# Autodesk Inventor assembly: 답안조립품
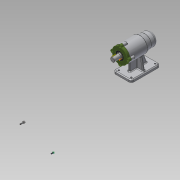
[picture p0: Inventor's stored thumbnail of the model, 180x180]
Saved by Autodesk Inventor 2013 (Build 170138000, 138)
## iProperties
Created: 2019-07
Part Number: 답안조립품
Document SubType Name: Assembly
Designer: Administrator
Author: Administrator
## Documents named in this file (12)
- C:\Users\Administrator\Desktop\490704V1055\답안조립품.iam
- C:\Users\Administrator\Desktop\490704V1055\본체.ipt
- C:\Users\Administrator\Desktop\490704V1055\V벨트풀리.ipt
- C:\Users\Administrator\Desktop\490704V1055\멈춤나사 M3.ipt
- C:\Users\Administrator\Desktop\490704V1055\베어링 6004.ipt
- C:\Users\Administrator\Desktop\490704V1055\베어링 51202.ipt
- C:\Users\Administrator\Desktop\490704V1055\볼트 M4.ipt
- C:\Users\Administrator\Desktop\490704V1055\어댑터슬리브.ipt
- C:\Users\Administrator\Desktop\490704V1055\오일 실.ipt
- C:\Users\Administrator\Desktop\490704V1055\축.ipt
- C:\Users\Administrator\Desktop\490704V1055\커버.ipt
- C:\Users\Administrator\Desktop\490704V1055\키 5 x 5 x 16.ipt
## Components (1 placed, 1 different names)
1. V벨트풀리:1
